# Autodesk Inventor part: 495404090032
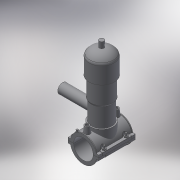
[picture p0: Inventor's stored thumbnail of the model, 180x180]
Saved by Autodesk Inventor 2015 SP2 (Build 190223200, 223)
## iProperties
Created: 2017-07
Part Number: 495404090032
Material: Generic
Description: PLASSON TAPPING VALVE 90-32
Document SubType Name: Modeling
Designer: KIM
Density: 1 g/cm^3
Appearance: Default
Author: KIM
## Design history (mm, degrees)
derived "495404-4954S4.ipt"
feature "Solid1::495404-4954S4.ipt"
feature "Solid2::495404-4954S4.ipt"
tag "TaggingFeature1"
body "Solid1"
body "Solid2"
other parameters: "d2" = 126, "d3" = 22.5, "d4" = 118, "d5" = 0, "d6" = 0.1, "d8" = 0, "d19" = 6, "d20" = 6, "d21" = 70.8, "d23" = 0, "d24" = 35.4, "d26" = 0, "d27" = 3, "d28" = 3, "d29" = 3, "d31" = 6, "d32" = 0, "d33" = 0, "d34" = 0.6, "d40" = 60.84, "d47" = 104.5, "d70" = 15, "d72" = 0, "d73" = 6, "d75" = 5, "d76" = 0, "d77" = 4.5, "d78" = 75, "d79" = 15, "d80" = 47.2, "d82" = 5 deg, "d84" = 4, "d85" = 14, "d86" = 0, "d87" = 3, "d88" = 0, "d89" = 1, "d90" = 1, "d91" = 94.4, "d92" = 0, "d93" = 0.5, "d94" = 47.36842, "d96" = 120.51, "d97" = 2.36, "d98" = 0, "d120" = 140 deg, "d121" = 24.228, "d122" = 20 deg, "d123" = 234, "d124" = 70.2, "d126" = 0, "d143" = 92.7, "d145" = 20.76923, "d149" = 1.35, "d150" = 22.84615, "d153" = 118, "d154" = 0, "d156" = 58.5, "d157" = 160 deg, "d159" = 5.4, "d161" = 1.35, "d162" = 70.8, "d163" = 0, "d164" = 45, "d167" = 9, "d168" = 57.07317, "d170" = 3, "d172" = 0, "d173" = 1, "d175" = 45, "d176" = 20 deg, "d177" = 6.3, "d178" = 27, "d180" = 0, "d183" = 10.8, "d184" = 5.04, "d185" = 38.35, "d186" = 38.35, "d187" = 58.5, "d188" = 8.1, "d189" = 6.3, "d190" = 0, "d191" = 87.75, "d193" = 6.8, "d194" = 2.95, "d195" = 90 deg, "d197" = 0, "d199" = 0, "d205" = 14.64, "d206" = 81.33333, "d207" = 244, "d208" = 224.48, "d209" = 207.4, "d210" = 200.08, "d211" = 146.4, "d212" = 85.4, "d213" = 65.88, "d214" = 73.2, "d216" = 19.52, "d217" = 70.76, "d218" = 80.52, "d222" = 0, "d223" = 117, "d224" = 126, "d225" = 46, "d226" = 32, "d229" = 126, "d230" = 0, "B_" = 126, "H_" = 126, "L_" = 118, "d_t" = 6, "d_1" = 32, "H_1" = 46, "H_2" = 244, "d148" = 1.35, "d160" = 1.35, "d169" = 3, "d192" = 6.8, "d228" = 25.6
